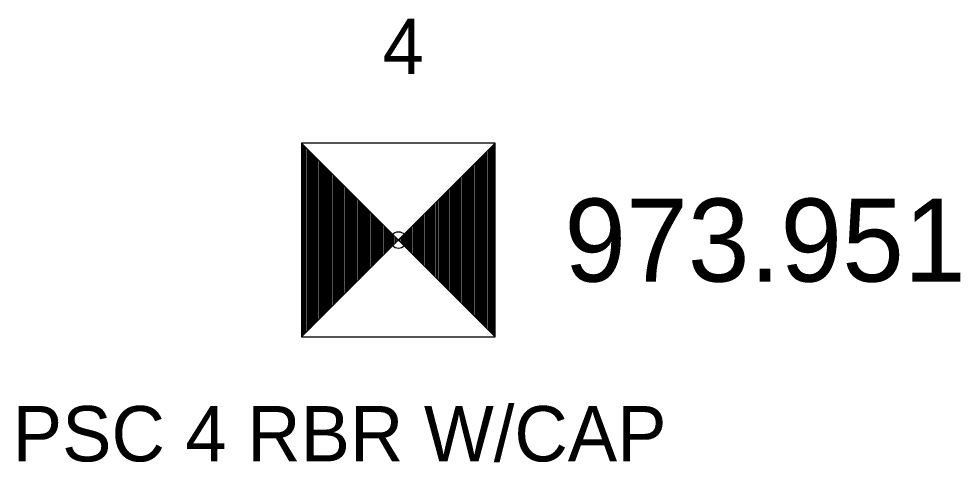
# Model space of a CAD drawing. Extents: x 1528109 to 1531398, y 1157799 to 1162548.
# Drawn here: x 1528285.31 to 1528302.32, y 1162394.09 to 1162402.11 of the extents above; entities that cross this region are included whole.
import ezdxf

# ---------------------------------------------------------------- set-up
doc = ezdxf.new("R2010")
doc.units = 0
for name, color, linetype in [('RD_HC_Survey', 7, 'Continuous'), ('RD_HC_Survey_ELEV', 7, 'Continuous'), ('RD_HC_txCode', 7, 'Continuous'), ('RD_SMD_Locator', 7, 'Continuous')]:
    doc.layers.add(name, color=color, linetype=linetype)

msp = doc.modelspace()

# ---------------------------------------------------------------- linework, layer by layer
at = {"layer": 'RD_HC_Survey'}
for p, q in [((1528290.42, 1162399.857), (1528293.92, 1162396.357)), ((1528293.92, 1162399.857), (1528290.42, 1162396.357)), ((1528290.445, 1162399.832), (1528290.445, 1162396.382)), ((1528293.895, 1162399.832), (1528293.895, 1162396.382)), ((1528290.469, 1162399.807), (1528290.469, 1162396.406)), ((1528290.494, 1162399.783), (1528290.494, 1162396.431)), ((1528290.519, 1162399.758), (1528290.519, 1162396.456)), ((1528290.544, 1162399.733), (1528290.544, 1162396.481)), ((1528290.568, 1162399.708), (1528290.568, 1162396.505)), ((1528290.593, 1162399.684), (1528290.593, 1162396.53)), ((1528290.618, 1162399.659), (1528290.618, 1162396.555)), ((1528293.722, 1162399.659), (1528293.722, 1162396.555)), ((1528293.747, 1162399.684), (1528293.747, 1162396.53)), ((1528293.771, 1162399.708), (1528293.771, 1162396.505)), ((1528293.796, 1162399.733), (1528293.796, 1162396.481)), ((1528293.821, 1162399.758), (1528293.821, 1162396.456)), ((1528293.846, 1162399.783), (1528293.846, 1162396.431)), ((1528293.87, 1162399.807), (1528293.87, 1162396.406)), ((1528290.643, 1162399.634), (1528290.643, 1162396.58)), ((1528290.667, 1162399.609), (1528290.667, 1162396.604)), ((1528290.692, 1162399.585), (1528290.692, 1162396.629)), ((1528290.717, 1162399.56), (1528290.717, 1162396.654)), ((1528290.742, 1162399.535), (1528290.742, 1162396.679)), ((1528290.766, 1162399.51), (1528290.766, 1162396.703)), ((1528290.791, 1162399.486), (1528290.791, 1162396.728)), ((1528293.549, 1162399.486), (1528293.549, 1162396.728)), ((1528293.573, 1162399.51), (1528293.573, 1162396.703)), ((1528293.598, 1162399.535), (1528293.598, 1162396.679)), ((1528293.623, 1162399.56), (1528293.623, 1162396.654)), ((1528293.648, 1162399.585), (1528293.648, 1162396.629)), ((1528293.672, 1162399.609), (1528293.672, 1162396.604)), ((1528293.697, 1162399.634), (1528293.697, 1162396.58)), ((1528290.816, 1162399.461), (1528290.816, 1162396.753)), ((1528290.841, 1162399.436), (1528290.841, 1162396.778)), ((1528290.865, 1162399.411), (1528290.865, 1162396.802)), ((1528290.89, 1162399.387), (1528290.89, 1162396.827)), ((1528290.915, 1162399.362), (1528290.915, 1162396.852)), ((1528290.94, 1162399.337), (1528290.94, 1162396.877)), ((1528290.964, 1162399.312), (1528290.964, 1162396.901)), ((1528293.375, 1162399.312), (1528293.375, 1162396.901)), ((1528293.4, 1162399.337), (1528293.4, 1162396.877)), ((1528293.425, 1162399.362), (1528293.425, 1162396.852)), ((1528293.45, 1162399.387), (1528293.45, 1162396.827)), ((1528293.474, 1162399.411), (1528293.474, 1162396.802)), ((1528293.499, 1162399.436), (1528293.499, 1162396.778)), ((1528293.524, 1162399.461), (1528293.524, 1162396.753)), ((1528290.989, 1162399.288), (1528290.989, 1162396.926)), ((1528291.014, 1162399.263), (1528291.014, 1162396.951)), ((1528291.039, 1162399.238), (1528291.039, 1162396.976)), ((1528291.063, 1162399.213), (1528291.063, 1162397)), ((1528291.088, 1162399.189), (1528291.088, 1162397.025)), ((1528291.113, 1162399.164), (1528291.113, 1162397.05)), ((1528291.138, 1162399.139), (1528291.138, 1162397.075)), ((1528293.202, 1162399.139), (1528293.202, 1162397.075)), ((1528293.227, 1162399.164), (1528293.227, 1162397.05)), ((1528293.252, 1162399.189), (1528293.252, 1162397.025)), ((1528293.276, 1162399.213), (1528293.276, 1162397)), ((1528293.301, 1162399.238), (1528293.301, 1162396.976)), ((1528293.326, 1162399.263), (1528293.326, 1162396.951)), ((1528293.351, 1162399.288), (1528293.351, 1162396.926)), ((1528291.162, 1162399.114), (1528291.162, 1162397.099)), ((1528291.187, 1162399.09), (1528291.187, 1162397.124)), ((1528291.212, 1162399.065), (1528291.212, 1162397.149)), ((1528291.237, 1162399.04), (1528291.237, 1162397.174)), ((1528291.261, 1162399.015), (1528291.261, 1162397.198)), ((1528291.286, 1162398.991), (1528291.286, 1162397.223)), ((1528291.311, 1162398.966), (1528291.311, 1162397.248)), ((1528293.029, 1162398.966), (1528293.029, 1162397.248)), ((1528293.054, 1162398.991), (1528293.054, 1162397.223)), ((1528293.078, 1162399.015), (1528293.078, 1162397.198)), ((1528293.103, 1162399.04), (1528293.103, 1162397.174)), ((1528293.128, 1162399.065), (1528293.128, 1162397.149)), ((1528293.153, 1162399.09), (1528293.153, 1162397.124)), ((1528293.177, 1162399.114), (1528293.177, 1162397.099)), ((1528291.336, 1162398.941), (1528291.336, 1162397.273)), ((1528291.36, 1162398.916), (1528291.36, 1162397.297)), ((1528291.385, 1162398.892), (1528291.385, 1162397.322)), ((1528291.41, 1162398.867), (1528291.41, 1162397.347)), ((1528291.435, 1162398.842), (1528291.435, 1162397.372)), ((1528291.459, 1162398.817), (1528291.459, 1162397.396)), ((1528291.484, 1162398.793), (1528291.484, 1162397.421)), ((1528292.856, 1162398.793), (1528292.856, 1162397.421)), ((1528292.88, 1162398.817), (1528292.88, 1162397.396)), ((1528292.905, 1162398.842), (1528292.905, 1162397.372)), ((1528292.93, 1162398.867), (1528292.93, 1162397.347)), ((1528292.955, 1162398.892), (1528292.955, 1162397.322)), ((1528292.979, 1162398.916), (1528292.979, 1162397.297)), ((1528293.004, 1162398.941), (1528293.004, 1162397.273)), ((1528291.509, 1162398.768), (1528291.509, 1162397.446)), ((1528291.533, 1162398.743), (1528291.533, 1162397.47)), ((1528291.558, 1162398.718), (1528291.558, 1162397.495)), ((1528291.583, 1162398.694), (1528291.583, 1162397.52)), ((1528291.608, 1162398.669), (1528291.608, 1162397.545)), ((1528291.632, 1162398.644), (1528291.632, 1162397.569)), ((1528291.657, 1162398.619), (1528291.657, 1162397.594)), ((1528292.682, 1162398.619), (1528292.682, 1162397.594)), ((1528292.707, 1162398.644), (1528292.707, 1162397.569)), ((1528292.732, 1162398.669), (1528292.732, 1162397.545)), ((1528292.757, 1162398.694), (1528292.757, 1162397.52)), ((1528292.781, 1162398.718), (1528292.781, 1162397.495)), ((1528292.806, 1162398.743), (1528292.806, 1162397.47)), ((1528292.831, 1162398.768), (1528292.831, 1162397.446)), ((1528291.682, 1162398.595), (1528291.682, 1162397.619)), ((1528291.707, 1162398.57), (1528291.707, 1162397.644)), ((1528291.731, 1162398.545), (1528291.731, 1162397.668)), ((1528291.756, 1162398.52), (1528291.756, 1162397.693)), ((1528291.781, 1162398.496), (1528291.781, 1162397.718)), ((1528291.806, 1162398.471), (1528291.806, 1162397.743)), ((1528292.534, 1162398.471), (1528292.534, 1162397.743)), ((1528292.559, 1162398.496), (1528292.559, 1162397.718)), ((1528292.583, 1162398.52), (1528292.583, 1162397.693)), ((1528292.608, 1162398.545), (1528292.608, 1162397.668)), ((1528292.633, 1162398.57), (1528292.633, 1162397.644)), ((1528292.658, 1162398.595), (1528292.658, 1162397.619)), ((1528291.83, 1162398.446), (1528291.83, 1162397.767)), ((1528291.855, 1162398.421), (1528291.855, 1162397.792)), ((1528291.88, 1162398.397), (1528291.88, 1162397.817)), ((1528291.905, 1162398.372), (1528291.905, 1162397.842)), ((1528291.929, 1162398.347), (1528291.929, 1162397.866)), ((1528291.954, 1162398.322), (1528291.954, 1162397.891)), ((1528291.979, 1162398.298), (1528291.979, 1162397.916)), ((1528292.361, 1162398.298), (1528292.361, 1162397.916)), ((1528292.385, 1162398.322), (1528292.385, 1162397.891)), ((1528292.41, 1162398.347), (1528292.41, 1162397.866)), ((1528292.435, 1162398.372), (1528292.435, 1162397.842)), ((1528292.46, 1162398.397), (1528292.46, 1162397.817)), ((1528292.484, 1162398.421), (1528292.484, 1162397.792)), ((1528292.509, 1162398.446), (1528292.509, 1162397.767)), ((1528292.004, 1162398.273), (1528292.004, 1162397.941)), ((1528292.028, 1162398.248), (1528292.028, 1162397.965)), ((1528292.053, 1162398.223), (1528292.053, 1162397.99)), ((1528292.078, 1162398.199), (1528292.078, 1162398.015)), ((1528292.103, 1162398.174), (1528292.103, 1162398.04)), ((1528292.127, 1162398.149), (1528292.127, 1162398.064)), ((1528292.152, 1162398.124), (1528292.152, 1162398.089)), ((1528292.187, 1162398.124), (1528292.187, 1162398.089)), ((1528292.212, 1162398.149), (1528292.212, 1162398.064)), ((1528292.237, 1162398.174), (1528292.237, 1162398.04)), ((1528292.262, 1162398.199), (1528292.262, 1162398.015)), ((1528292.286, 1162398.223), (1528292.286, 1162397.99)), ((1528292.311, 1162398.248), (1528292.311, 1162397.965)), ((1528292.336, 1162398.273), (1528292.336, 1162397.941))]:
    msp.add_line(p, q, dxfattribs=at)
msp.add_lwpolyline([(1528293.92, 1162399.857), (1528290.42, 1162399.857), (1528290.42, 1162396.357), (1528293.92, 1162396.357)], close=True, dxfattribs=at)
at = {"layer": 'RD_SMD_Locator'}
msp.add_circle((1528292.17, 1162398.107), 0.15, dxfattribs=at)

# ---------------------------------------------------------------- texts
at = {"layer": 'RD_HC_Survey_ELEV'}
msp.add_text('973.951', height=1.5, dxfattribs=at).set_placement((1528295.17, 1162397.357))
at = {"layer": 'RD_HC_txCode'}
for s, p in [('4', (1528291.886, 1162401.107)), ('PSC 4 RBR W/CAP', (1528285.201, 1162394.107))]:
    msp.add_text(s, height=1, dxfattribs=at).set_placement(p)

doc.saveas('drawing.dxf')
